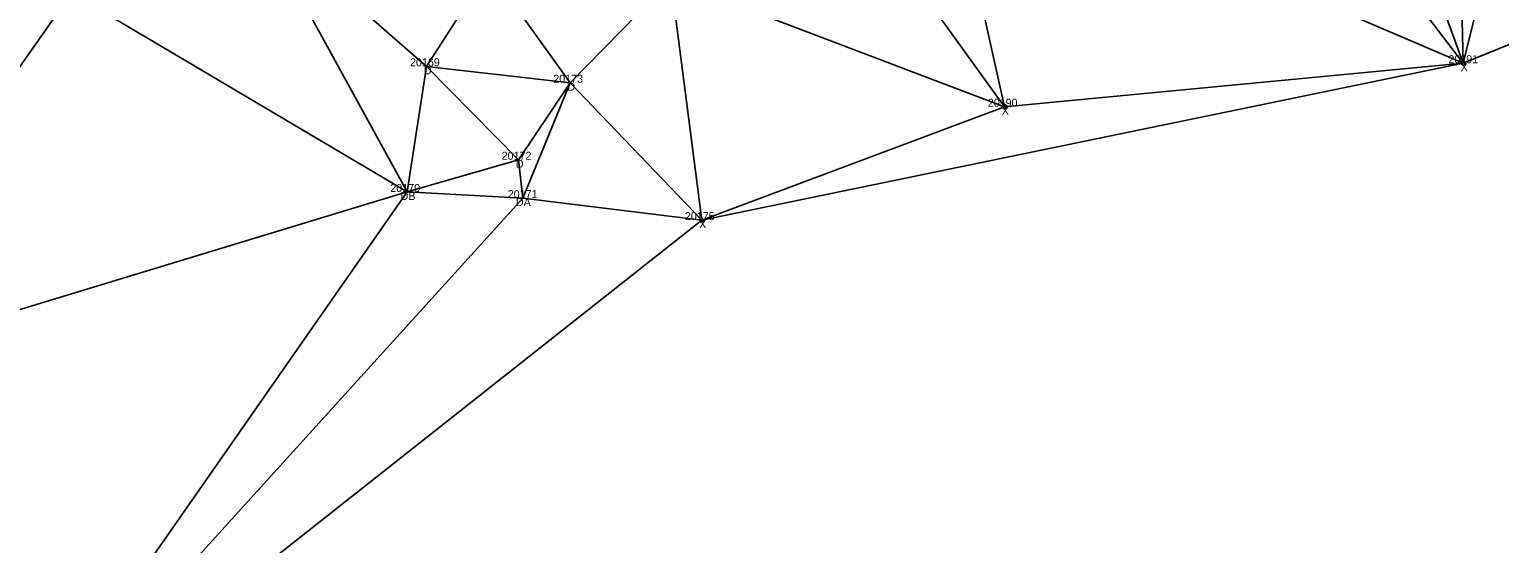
# Model space of a CAD drawing. Extents: x 1966740 to 1969291, y 1117379 to 1118460.
# Drawn here: x 1967228 to 1967411.8, y 1117539.9 to 1117604.2 of the extents above; entities that cross this region are included whole.
import ezdxf

# ---------------------------------------------------------------- set-up
doc = ezdxf.new("R2010")
doc.units = 0
for name, color, linetype in [('Level 30', 7, 'Continuous'), ('Level 35', 7, 'Continuous'), ('Level 50', 7, 'Continuous'), ('Level 52', 7, 'Continuous'), ('Level 58', 7, 'Continuous'), ('Level 62', 7, 'Continuous'), ('Level 8', 7, 'Continuous')]:
    doc.layers.add(name, color=color, linetype=linetype)

msp = doc.modelspace()

# ---------------------------------------------------------------- linework, layer by layer
at = {"layer": 'Level 30'}
for centre in [(1967407.22, 1117599.96), (1967349.88, 1117594.52), (1967312.07, 1117580.34)]:
    msp.add_circle(centre, 0.25, dxfattribs=at)
at = {"layer": 'Level 35'}
for points in [[(1967405.39, 1117677.87), (1967428.8, 1117686.6), (1967407.22, 1117599.96)], [(1967407.22, 1117599.96), (1967428.8, 1117686.6), (1967513.9, 1117643.33)], [(1967381.99, 1117669.13), (1967405.39, 1117677.87), (1967407.22, 1117599.96)], [(1967360.29, 1117661.3), (1967381.99, 1117669.13), (1967407.22, 1117599.96)], [(1967342.53, 1117627.68), (1967360.29, 1117661.3), (1967407.22, 1117599.96)], [(1967308.21, 1117610.4), (1967325.62, 1117628.22), (1967349.88, 1117594.52)], [(1967325.62, 1117628.22), (1967342.53, 1117627.68), (1967349.88, 1117594.52)], [(1967342.53, 1117627.68), (1967407.22, 1117599.96), (1967349.88, 1117594.52)], [(1967233.29, 1117608.76), (1967256.44, 1117618.12), (1967275.25, 1117583.86)], [(1967256.44, 1117618.12), (1967285.44, 1117611.7), (1967277.66, 1117599.57)], [(1967256.44, 1117618.12), (1967277.66, 1117599.57), (1967275.25, 1117583.86)], [(1967277.66, 1117599.57), (1967285.44, 1117611.7), (1967295.61, 1117597.52)], [(1967285.44, 1117611.7), (1967308.21, 1117610.4), (1967295.61, 1117597.52)], [(1967295.61, 1117597.52), (1967308.21, 1117610.4), (1967312.07, 1117580.34)], [(1967308.21, 1117610.4), (1967349.88, 1117594.52), (1967312.07, 1117580.34)], [(1967199.69, 1117560.93), (1967210.14, 1117599.41), (1967233.29, 1117608.76)], [(1967199.69, 1117560.93), (1967233.29, 1117608.76), (1967275.25, 1117583.86)], [(1967312.07, 1117580.34), (1967349.88, 1117594.52), (1967407.22, 1117599.96)], [(1967275.25, 1117583.86), (1967277.66, 1117599.57), (1967289.16, 1117587.89)], [(1967277.66, 1117599.57), (1967295.61, 1117597.52), (1967289.16, 1117587.89)], [(1967289.16, 1117587.89), (1967295.61, 1117597.52), (1967289.71, 1117583.09)], [(1967289.71, 1117583.09), (1967295.61, 1117597.52), (1967312.07, 1117580.34)], [(1967275.25, 1117583.86), (1967289.16, 1117587.89), (1967289.71, 1117583.09)], [(1967199.69, 1117560.93), (1967275.25, 1117583.86), (1967224.58, 1117511.21)], [(1967224.58, 1117511.21), (1967275.25, 1117583.86), (1967289.71, 1117583.09)], [(1967224.58, 1117511.21), (1967289.71, 1117583.09), (1967312.07, 1117580.34)]]:
    msp.add_lwpolyline(points, close=True, dxfattribs=at)
at = {"layer": 'Level 50'}
for centre in [(1967277.66, 1117599.57), (1967295.61, 1117597.52), (1967289.16, 1117587.89), (1967275.25, 1117583.86), (1967289.71, 1117583.09)]:
    msp.add_circle(centre, 0.001, dxfattribs=at)
at = {"layer": 'Level 8'}
for points in [[(1967289.71, 1117583.09), (1967289.16, 1117587.89), (1967295.61, 1117597.52), (1967308.21, 1117610.4), (1967325.87, 1117628.48), (1967333.04, 1117643.27), (1967334.06, 1117655.75), (1967333.75, 1117659.51), (1967340.03, 1117669.86)], [(1967308.82, 1117656.67), (1967314.11, 1117648.69), (1967313.63, 1117644.86), (1967310.07, 1117639.65), (1967297.74, 1117623.99), (1967285.44, 1117611.7), (1967277.66, 1117599.57), (1967275.25, 1117583.86)]]:
    msp.add_lwpolyline(points, dxfattribs=at)

# ---------------------------------------------------------------- texts
at = {"layer": 'Level 52'}
for s, p in [('20191', (1967405.36, 1117599.96)), ('20190', (1967347.8, 1117594.52)), ('20175', (1967309.95, 1117580.34))]:
    msp.add_text(s, height=1, dxfattribs=at).set_placement(p)
at = {"layer": 'Level 58'}
for s, p in [('20169', (1967275.6, 1117599.57)), ('D', (1967277.33, 1117598.57)), ('20173', (1967293.5, 1117597.52)), ('D', (1967295.28, 1117596.52)), ('20172', (1967287.05, 1117587.89)), ('D', (1967288.83, 1117586.89)), ('20170', (1967273.14, 1117583.86)), ('DB', (1967274.42, 1117582.86)), ('20171', (1967287.81, 1117583.09)), ('DA', (1967288.83, 1117582.09))]:
    msp.add_text(s, height=1, dxfattribs=at).set_placement(p)
at = {"layer": 'Level 62'}
for p in [(1967406.89, 1117598.96), (1967349.55, 1117593.52), (1967311.73, 1117579.34)]:
    msp.add_text('X', height=1, dxfattribs=at).set_placement(p)

doc.saveas('drawing.dxf')
